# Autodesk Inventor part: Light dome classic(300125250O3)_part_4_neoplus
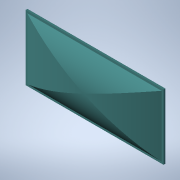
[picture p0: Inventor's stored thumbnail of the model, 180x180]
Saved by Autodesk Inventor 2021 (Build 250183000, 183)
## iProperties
Created: 2026-04
Part Number: Light dome classic(300125250O3)_part_4_neoplus
Material: Generic
Catalog Web Link: www.3dfindit.com
Description: Light dome classic_part_4_neoplus-
Vendor: KINGSPAN
Document SubType Name: Modeling
Designer: psAdmin
Manufacturer: KINGSPAN
Mass: 309116 g
Surface Area: 57706.7 cm^2
Volume: 309116 cm^3
Density: 1 g/cm^3
Appearance: PSOLRGB-194-255-255
Category: PARTsolutions
Company: KINGSPAN
Title: Light dome classic(300125250O3)_part_4_neoplus
Author: Cadenas PARTsolutions
PSOL_IDENT_0: {$CADENAS_DATA/23d-libs/kingspan_kla/light_dome_classic_neoplus/parts/part_4.prj},278 {VTYP=3D},{NB=
PSOL_IDENT_1: Light dome classic(300125250O3)_part_4_neoplus},{LINA=Light dome classic(300125250O3)_part_4_neoplus
PSOL_IDENT_2: },{NN=Light dome classic_part_4_neoplus},{DATE=20.03.2025 09:30:52},{GEOMDATE=01.07.2024 05:57:57},{
PSOL_IDENT_3: VERSION=},{LINEID=10},{WBVAR=LODLEVEL,L,W,TG,TS},{WBNUMERIC=W}  {NB=Light dome classic(300125250O3)_
PSOL_IDENT_4: part_4_neoplus},{LINA=Light dome classic(300125250O3)_part_4_neoplus},{KT=DUMMY},{IDNR=},{PN=Light d
PSOL_IDENT_5: ome classic},{LODLEVEL=300},{L=125},{W=250},{WX=125,250,300},{TG=O},{TS=3},{TSX='3','acrylic shell w
PSOL_IDENT_6: ith Polycarbonate','4','2 layers of acrylic shell + 1  Polycarbonate panel','5','1 layers of acrylic
PSOL_IDENT_7: shell + 1 polycarbonate panel + aerogel'},{LX=1250},{XWX=2500},{VER=2},{HEI=1214.941},{TOP=400},{NO=
PSOL_IDENT_8: 2},{HEIGHT=220},{SEC=30}
NB: Light dome classic(300125250O3)_part_4_neoplus
NN: Light dome classic_part_4_neoplus
NBSYN: $PN.($LODLEVEL.$L.$W.$TG.$TS.)_part_4_neoplus
LINA: Light dome classic(300125250O3)_part_4_neoplus
CATALOG: Light + Air
PN: Light dome classic
LODLEVEL: 300
L: 125
W: 250
TG: opal
TS: acrylic shell with Polycarbonate
SUPPLIER: KINGSPAN
ARTICLENO: Light dome classic(300125250O3)_part_4_neoplus
BOMINFO: Light dome classic(300125250O3)_part_4_neoplus
CREATOR: CADENAS GmbH
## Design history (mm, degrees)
sketch "Sketch_9"
  geometry: L1 (1150, 0)-(1150, 106.946); L2 (-1150, 106.946)-(-1150, 0); L3 (-1150, 0)-(1150, 0); A1 r 3666.824 centre (0, -3374.878) between (1150, 106.946) and (-1150, 106.946)
  constraints: 6 end point, 2 point on circle, 1 centre point
extrude "Extrusion1" join sketch "Sketch_9" stored distance "d0" = 2500; taper "d1" = 0 deg
sketch "Sketch_2"
  geometry: L1 (1256, 103.596)-(-1256, 103.596); L2 (-1256, 103.596)-(-1256, 71.946); L3 (-1256, 71.946)-(1256, 71.946); L4 (1256, 71.946)-(1256, 103.596)
  constraints: 8 end point
extrude "Extrusion2" join sketch "Sketch_2" stored distance "d2" = 2500; taper "d3" = 0 deg
sketch "Sketch_3"
  geometry: L1 (-655, 103.596)-(-655, 71.946); L2 (-655, 71.946)-(655, 71.946); L3 (655, 71.946)-(655, 103.596); L4 (655, 103.596)-(-655, 103.596)
  constraints: 8 end point
extrude "Extrusion3" join sketch "Sketch_3" stored distance "d4" = 5000; taper "d5" = 0 deg
sketch "Sketch_4"
  geometry: L1 (-3058, 103.596)-(-3058, -128.054); L2 (-3058, -128.054)-(3058, -128.054); L3 (3058, -128.054)-(3058, 103.596); L4 (3058, 103.596)-(558, 103.596); L5 (558, 103.596)-(558, 71.946); L6 (558, 71.946)-(-558, 71.946); L7 (-558, 71.946)-(-558, 103.596); L8 (-558, 103.596)-(-3058, 103.596)
  constraints: 16 end point
extrude "Extrusion4" cut sketch "Sketch_4" stored distance "d6" = 5000; taper "d7" = 0 deg
sketch "Sketch_17"
  geometry: L1 (1000, -16104.45)-(-1000, -16104.45); L2 (-135, 100)-(-135, -106.95); L3 (-135, -106.95)-(135, -106.95); L4 (135, -106.95)-(135, 100); A1 r 1825 centre (0, -1720) between (135, 100) and (-135, 100)
  constraints: 8 end point, 2 point on circle, 1 centre point
revolve "Revolution1" sketch "Sketch_17" stored, may be unused: angle "d8" = 360 deg
sketch "Sketch_13"
  geometry: L1 (1182, 103.596)-(1130, 103.596); L2 (1130, 103.596)-(1130, 71.946); L3 (1130, 71.946)-(-1130, 71.946); L4 (-1130, 71.946)-(-1130, 103.596); L5 (-1130, 103.596)-(-1182, 103.596); L6 (-1182, 103.596)-(-1182, 61.946); L7 (-1182, 61.946)-(1182, 61.946); L8 (1182, 61.946)-(1182, 103.596)
  constraints: 16 end point
extrude "Extrusion5" join sketch "Sketch_13" stored distance "d9" = 1250; taper "d10" = 0 deg
sketch "Sketch_14"
  geometry: L1 (3650, 103.596)-(1182, 103.596); L2 (1182, 103.596)-(1182, 71.946); L3 (1182, 71.946)-(-1182, 71.946); L4 (-1182, 71.946)-(-1182, 103.596); L5 (-1182, 103.596)-(-3650, 103.596); L6 (-3650, 103.596)-(-3650, -128.054); L7 (-3650, -128.054)-(3650, -128.054); L8 (3650, -128.054)-(3650, 103.596)
  constraints: 16 end point
extrude "Extrusion6" cut sketch "Sketch_14" stored distance "d11" = 2500; taper "d12" = 0 deg
sketch "Sketch_15"
  geometry: L1 (3049, 1416.667)-(-3049, 1416.667); L2 (-3049, 1416.667)-(-3049, 0); L3 (-3049, 0)-(-558, 0); L4 (-558, 0)-(-558, 103.596); L5 (-558, 103.596)-(-525, 103.596); L6 (-525, 103.596)-(-525, 106.946); L7 (525, 106.946)-(525, 103.596); L8 (525, 103.596)-(558, 103.596); L9 (558, 103.596)-(558, 0); L10 (558, 0)-(3049, 0); L11 (3049, 0)-(3049, 1416.667); A1 r 837.432 centre (0, -545.486) between (525, 106.946) and (-525, 106.946)
  constraints: 22 end point, 2 point on circle, 1 centre point
extrude "Extrusion7" cut sketch "Sketch_15" stored distance "d13" = 2500; taper "d14" = 0 deg
node "IP_4_XY"
node "IP_4_YZ"
node "IP_4_ZX"
node "IP_4_X"
node "IP_4_Y"
node "IP_4_Z"
node "IP_4_Center"
body "Solid1"
